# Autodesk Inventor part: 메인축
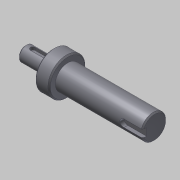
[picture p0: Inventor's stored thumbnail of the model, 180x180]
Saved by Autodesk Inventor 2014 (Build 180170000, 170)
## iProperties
Created: 2018-09
Part Number: 메인축
Document SubType Name: Modeling
Density: 7.86 g/cm^3
Material: 강철, 연강
Appearance: 강철
Mass: 251.954 g
Surface Area: 77.4403 cm^2
Volume: 32.0552 cm^3
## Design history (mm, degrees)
sketch "스케치1"
  geometry: L1 (34.997, -37.5)-(34.997, -77.5) reference; L2 (46.5, -38.401)-(46.5, -76.599) reference; L3 (12.497, -57.5)-(116.5, -57.5); L4 (12.497, -63.5)-(34.997, -63.5); L5 (34.997, -72.5)-(46.5, -72.5); L6 (46.5, -67.5)-(116.5, -67.5); L7 (116.5, -67.5)-(116.5, -57.5); L8 (12.497, -63.5)-(12.497, -57.5); 2 further points
  constraints: 12 end point, 5 point on line, 4 perpendicular, 1 midpoint, 1 parallel
  dimensions: "d0" = 20 diameter of L6 L3; "d1" = 30 diameter of L5 L3; "d2" = 22.5 distance of L4.start L4.end; "d3" = 70 distance of L6.start L6.end; "d5" = 12 diameter of L4 L3
revolve "회전1" sketch "스케치1" stored, may be unused: angle "d4" = 90 deg
chamfer "모따기1" distance "d6" = 1; stored, may be unused: second distance "d7" = 2, angle "d8" = 45 deg
node "작업 평면1"
sketch "스케치2"
  geometry: L1 (-11.25, -5)-(-11.25, 5) reference; L2 (-5.25, 2)-(4.75, 2); L3 (4.75, -2)-(-5.25, -2); A1 r 2 centre (4.75, 0) between (4.75, -2) and (4.75, 2); A2 r 2 centre (-5.25, 0) between (-5.25, 2) and (-5.25, -2); 2 further points
  constraints: 4 end point, 4 point on circle, 4 tangent, 2 centre point, 1 horizontal alignment, 1 midpoint, 1 parallel, 1 perpendicular
  dimensions: "d9" = 4 distance between parallel lines of L3 L2; "d10" = 14 dimension on A1 A2; "d11" = 4 distance edge to line of A2 L1
extrude "돌출1" cut sketch "스케치2" distance "d12" = 2.5; taper "d13" = 0 deg
node "작업 평면2"
sketch "스케치3"
  geometry: L1 (35, 9)-(35, -9) reference; L2 (35, 3)-(20, 3); L3 (20, -3)-(35, -3); A1 r 3 centre (20, 0) between (20, 3) and (20, -3); 2 further points
  constraints: 4 end point, 2 perpendicular, 2 point on circle, 2 point on line, 2 tangent, 1 centre point, 1 horizontal alignment, 1 midpoint
  dimensions: "d14" = 6 distance between parallel lines of L3 L2; "d15" = 18 dimension on A1 L1
extrude "돌출2" cut sketch "스케치3" distance "d16" = 3.5; taper "d17" = 0 deg
node "솔리드1"
node "참조1"
node "참조2"
